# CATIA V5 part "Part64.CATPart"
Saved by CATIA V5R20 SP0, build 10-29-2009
Part number: FA 042200-1
Revision: ANY
Definition: UNKNOWN
Nomenclature: FA 042200-1
Source: Unknown
Bounding box of the stored display mesh (mm): x 0.374 to 3.8, y -1.58 to 1.58, z -1.58 to 1.58
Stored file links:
  C:\Users\Utente\Desktop\IO LAVORO\3D X SITO CF\CUMSA\3D files FA\FA 042212-21\Part64.CATPart

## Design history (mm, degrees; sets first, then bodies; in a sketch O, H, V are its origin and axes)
Body1 "Cortar-Extruir2" (main body)
  Solid1: solid without history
